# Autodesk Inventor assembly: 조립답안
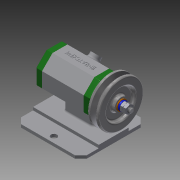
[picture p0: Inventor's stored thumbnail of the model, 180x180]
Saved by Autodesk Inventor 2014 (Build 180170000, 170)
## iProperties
Created: 2018-06
Part Number: 조립답안
Document SubType Name: Assembly
Designer: kh
Author: kh
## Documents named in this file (15)
- C:\Users\kh\Desktop\480607V1020\조립답안.iam
- C:\Users\kh\Desktop\480607V1020\본체.ipt
- C:\Users\kh\Desktop\480607V1020\축.ipt
- C:\Users\kh\Desktop\480607V1020\V벨트풀리.ipt
- C:\Users\kh\Desktop\480607V1020\키 3x3x12.ipt
- 키 3x3x12.ipt
- C:\Users\kh\Desktop\480607V1020\와셔 8x17.ipt
- C:\Users\kh\Desktop\480607V1020\너트 M8.ipt
- 너트 M8.ipt
- C:\Users\kh\Desktop\480607V1020\스프링와셔 8.ipt
- C:\Users\kh\Desktop\480607V1020\앞커버.ipt
- C:\Users\kh\Desktop\480607V1020\뒤커버.ipt
- C:\Users\kh\Desktop\480607V1020\오일 실 15 25 7.ipt
- C:\Users\kh\Desktop\480607V1020\베어링 15x32x9.ipt
- C:\Users\kh\Desktop\480607V1020\볼트 M4x12.ipt
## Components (1 placed, 1 different names)
1. V벨트풀리:1 — Insert:3, Insert:4, Mate:2
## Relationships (3: Insert 2, Mate 1)
- Insert:3: V벨트풀리:1
- Insert:4: V벨트풀리:1
- Mate:2: V벨트풀리:1
